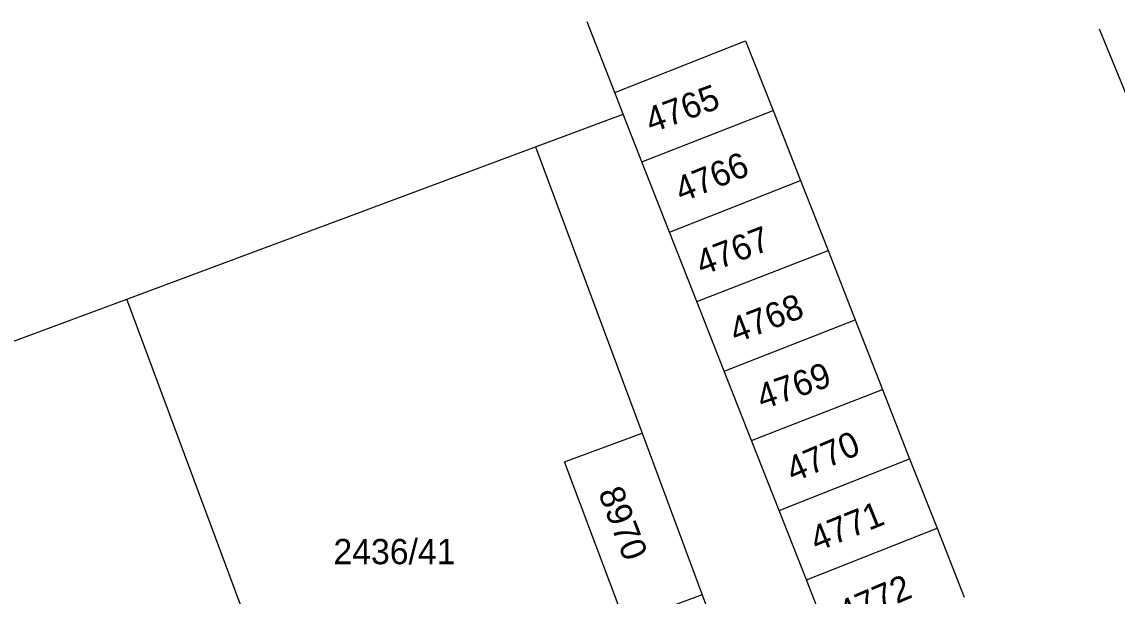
# Model space of a CAD drawing. Extents: x -566117 to -565580, y -1202428 to -1201938.
# Drawn here: x -565829.36 to -565781.63, y -1201970.24 to -1201945.24 of the extents above; entities that cross this region are included whole.
import ezdxf

# ---------------------------------------------------------------- set-up
doc = ezdxf.new("R2010")
doc.units = 0
doc.layers.add('Implicitní', color=7, linetype='Continuous')
doc.layers.add('Katastr', color=7, linetype='Continuous')

# ---------------------------------------------------------------- blocks, each defined once
blk = doc.blocks.new('A$C69D74C1E')
at = {"layer": 'Katastr'}
for p, q in [((261.41, 120.13), (260.2, 123.2)), ((283.82, 119.73), (282.53, 122.89)), ((261.41, 120.13), (267.11, 122.38)), ((267.11, 122.38), (268.31, 119.34)), ((261.78, 119.18), (261.41, 120.13)), ((262.59, 117.11), (268.31, 119.34)), ((268.31, 119.34), (269.5, 116.29)), ((257.96, 117.76), (261.78, 119.18)), ((262.59, 117.11), (261.78, 119.18)), ((240.15, 111.13), (257.96, 117.76)), ((257.96, 117.76), (262.6, 105.29)), ((263.8, 114.04), (262.59, 117.11)), ((263.8, 114.04), (269.5, 116.29)), ((269.5, 116.29), (270.7, 113.25)), ((264.99, 111.02), (263.8, 114.04)), ((264.99, 111.02), (270.7, 113.25)), ((270.7, 113.25), (271.88, 110.23)), ((222.34, 104.51), (240.15, 111.13)), ((257.59, 64.28), (240.15, 111.13)), ((266.18, 107.99), (264.99, 111.02)), ((266.18, 107.99), (271.88, 110.23)), ((271.88, 110.23), (273.07, 107.2)), ((267.37, 104.97), (266.18, 107.99)), ((267.37, 104.97), (273.07, 107.2)), ((273.07, 107.2), (274.25, 104.18)), ((262.6, 105.29), (265.22, 98.25)), ((268.57, 101.92), (267.37, 104.97)), ((268.57, 101.92), (274.25, 104.18)), ((274.25, 104.18), (275.45, 101.16)), ((269.76, 98.91), (268.57, 101.92)), ((269.76, 98.91), (275.45, 101.16)), ((275.45, 101.16), (276.64, 98.15)), ((270.95, 95.89), (269.76, 98.91))]:
    blk.add_line(p, q, dxfattribs=at)
for points in [[(265.22, 98.25), (261.86, 97.02), (259.22, 104.04), (262.6, 105.29)], [(265.22, 98.25), (274.87, 72.31), (272.11, 69.69), (257.59, 64.28)]]:
    blk.add_lwpolyline(points, dxfattribs=at)
for s, rotation, p in [('4765', 20, (262.995, 118.355)), ('4766', 22, (264.313, 115.33)), ('4767', 21, (265.209, 112.142)), ('4768', 21, (266.679, 109.202)), ('4769', 19, (267.831, 106.307)), ('4770', 23, (269.177, 103.138)), ('8970', 291, (260.672, 102.711)), ('4771', 22, (270.203, 100.12)), ('4772', 23, (271.427, 96.888))]:
    blk.add_text(s, height=1.1, rotation=rotation, dxfattribs=at).set_placement(p)
blk.add_text('2436/41', height=1.1, dxfattribs=at).set_placement((249.15, 99.587))

msp = doc.modelspace()

# ---------------------------------------------------------------- block references
at = {"layer": 'Implicitní'}
msp.add_blockref('A$C69D74C1E', (-566064.93, -1202068.44), dxfattribs=at)

doc.saveas('drawing.dxf')
